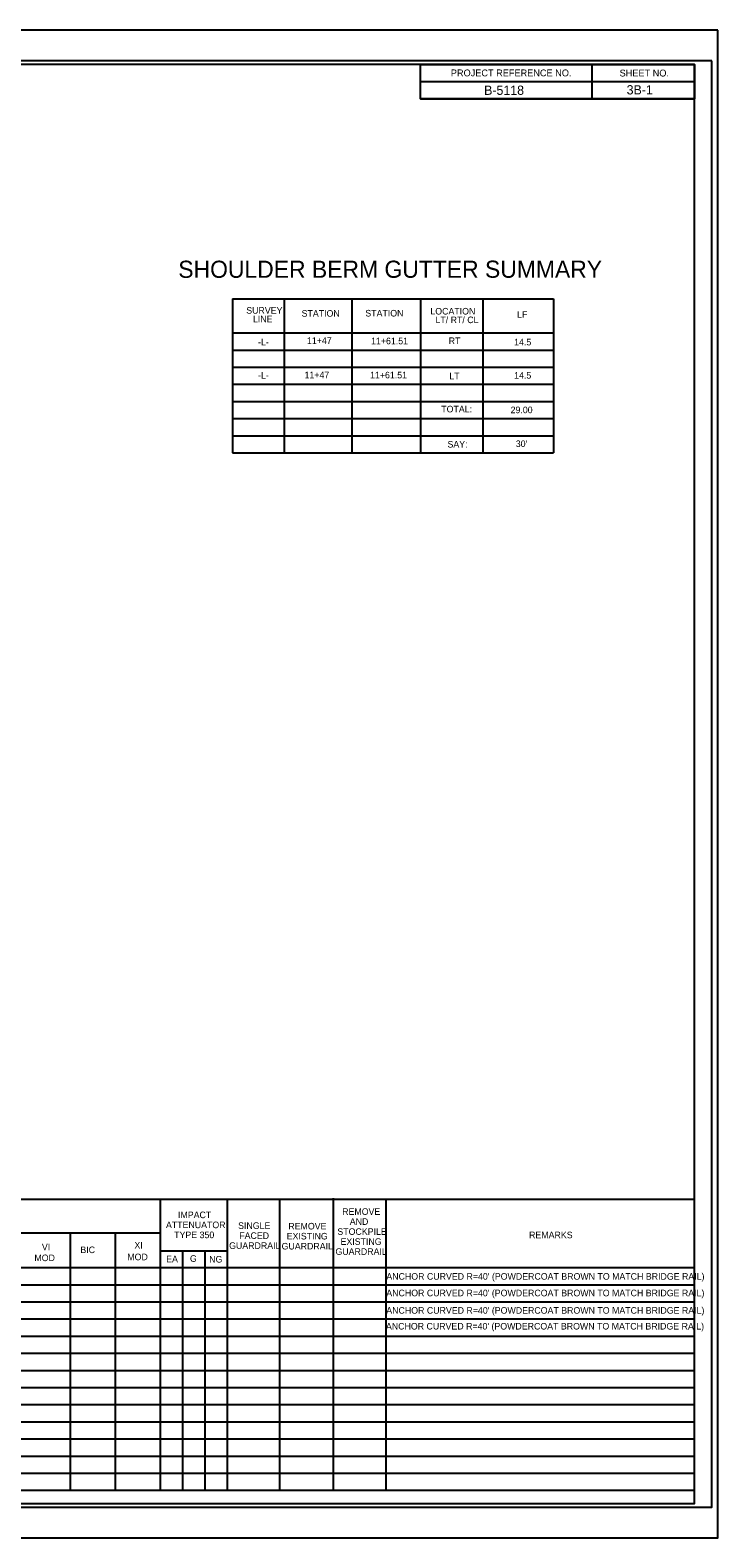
# Model space of a CAD drawing. Extents: x 1729980.3 to 1730027.7, y 539928.4 to 539950.4.
# Drawn here: x 1730003.96 to 1730014, y 539928.38 to 539950.38 of the extents above; entities that cross this region are included whole.
import ezdxf

# ---------------------------------------------------------------- set-up
doc = ezdxf.new("R2010")
doc.units = 0
for name, color, linetype in [('Default', 7, 'Continuous'), ('Sheet Cutting Line CELL', 7, 'Continuous'), ('Sheet Data Field CELL', 7, 'Continuous'), ('Sheet Plot Border Inside CELL', 7, 'Continuous'), ('Sheet Plot Border Outside CELL', 7, 'Continuous'), ('Sheet Summary Combination CELL', 7, 'Continuous'), ('Sheet Summary Combination Grid CELL', 7, 'Continuous')]:
    doc.layers.add(name, color=color, linetype=linetype)

msp = doc.modelspace()

# ---------------------------------------------------------------- linework, layer by layer
at = {"layer": 'Sheet Cutting Line CELL'}
msp.add_line((1730013.998, 539950.377), (1729980.318, 539950.377), dxfattribs=at)
at = {"layer": 'Sheet Plot Border Inside CELL'}
msp.add_lwpolyline([(1730013.908, 539949.928), (1729980.578, 539949.928), (1729980.578, 539928.826), (1730013.908, 539928.826)], close=True, dxfattribs=at)
at = {"layer": 'Sheet Plot Border Outside CELL'}
msp.add_lwpolyline([(1730013.998, 539950.377), (1729980.318, 539950.377), (1729980.318, 539928.377), (1730013.998, 539928.377)], close=True, dxfattribs=at)
at = {"layer": 'Sheet Summary Combination CELL'}
for p, q in [((1730012.158, 539949.876), (1730012.158, 539949.376)), ((1730009.657, 539949.626), (1730013.658, 539949.626)), ((1730009.657, 539949.376), (1730013.658, 539949.376)), ((1730009.737, 539946.458), (1730009.737, 539946.458)), ((1730009.862, 539946.456), (1730009.862, 539946.456)), ((1730010.043, 539946.46), (1730010.043, 539946.46)), ((1730010.155, 539946.458), (1730010.155, 539946.458))]:
    msp.add_line(p, q, dxfattribs=at)
for points in [[(1730013.658, 539949.877), (1729983.658, 539949.877), (1729983.658, 539928.877), (1730013.658, 539928.877)], [(1730009.657, 539949.877), (1730013.658, 539949.877), (1730013.658, 539949.376), (1730009.657, 539949.376)]]:
    msp.add_lwpolyline(points, close=True, dxfattribs=at)
at = {"layer": 'Sheet Summary Combination Grid CELL'}
for p, q in [((1730006.912, 539946.459), (1730011.601, 539946.459)), ((1730006.912, 539946.459), (1730006.912, 539944.209)), ((1730007.668, 539946.459), (1730007.668, 539944.209)), ((1730008.654, 539946.459), (1730008.654, 539944.209)), ((1730009.66, 539946.459), (1730009.66, 539944.209)), ((1730010.568, 539946.45), (1730010.568, 539944.2)), ((1730011.601, 539946.459), (1730011.601, 539944.209)), ((1730006.912, 539945.959), (1730011.601, 539945.959)), ((1730006.912, 539945.709), (1730011.601, 539945.709)), ((1730006.912, 539945.459), (1730011.601, 539945.459)), ((1730006.912, 539945.209), (1730011.601, 539945.209)), ((1730006.912, 539944.959), (1730011.601, 539944.959)), ((1730006.912, 539944.709), (1730011.601, 539944.709)), ((1730006.912, 539944.459), (1730011.601, 539944.459)), ((1730006.912, 539944.209), (1730011.601, 539944.209)), ((1729983.658, 539933.321), (1730013.658, 539933.321)), ((1730005.857, 539933.321), (1730005.857, 539929.071)), ((1730006.834, 539933.321), (1730006.834, 539929.071)), ((1730007.598, 539933.321), (1730007.598, 539929.071)), ((1730008.385, 539933.332), (1730008.385, 539929.082)), ((1730009.151, 539933.321), (1730009.151, 539929.071)), ((1730005.857, 539932.821), (1729996.314, 539932.821)), ((1730004.545, 539932.821), (1730004.545, 539929.071)), ((1730005.201, 539932.821), (1730005.201, 539929.071)), ((1730005.857, 539932.566), (1730006.829, 539932.566)), ((1730006.182, 539932.566), (1730006.184, 539929.071)), ((1730006.509, 539932.566), (1730006.511, 539929.071)), ((1729983.658, 539932.321), (1730013.658, 539932.321)), ((1729983.658, 539932.071), (1730013.658, 539932.071)), ((1729983.658, 539931.821), (1730013.658, 539931.821)), ((1729983.658, 539931.571), (1730013.658, 539931.571)), ((1729983.658, 539931.321), (1730013.658, 539931.321)), ((1729983.658, 539931.321), (1730013.658, 539931.321)), ((1729983.658, 539931.071), (1730013.658, 539931.071)), ((1729983.658, 539930.821), (1730013.658, 539930.821)), ((1729983.658, 539930.571), (1730013.658, 539930.571)), ((1729983.658, 539930.321), (1730013.658, 539930.321)), ((1729983.658, 539930.071), (1730013.658, 539930.071)), ((1729983.658, 539929.821), (1730013.658, 539929.821)), ((1729983.658, 539929.571), (1730013.658, 539929.571)), ((1729983.658, 539929.321), (1730013.658, 539929.321)), ((1729983.658, 539929.071), (1730013.658, 539929.071)), ((1729983.658, 539929.071), (1730013.658, 539929.071))]:
    msp.add_line(p, q, dxfattribs=at)

# ---------------------------------------------------------------- texts
at = {"layer": 'Default'}
for s, p in [('-L-', (1730007.287, 539945.777)), ('11+47', (1730008.001, 539945.799)), ('11+61.51', (1730008.937, 539945.794)), ('RT', (1730010.069, 539945.797)), ('14.5', (1730011.025, 539945.777)), ('-L-', (1730007.287, 539945.292)), ('11+47', (1730007.966, 539945.298)), ('11+61.51', (1730008.922, 539945.296)), ('LT', (1730010.08, 539945.283)), ('14.5', (1730011.025, 539945.292)), ('29.00', (1730010.973, 539944.788)), ("30'", (1730011.049, 539944.294)), ("ANCHOR CURVED R=40' (POWDERCOAT BROWN TO MATCH BRIDGE RAIL)", (1730009.16, 539932.144)), ("ANCHOR CURVED R=40' (POWDERCOAT BROWN TO MATCH BRIDGE RAIL)", (1730009.159, 539931.902)), ("ANCHOR CURVED R=40' (POWDERCOAT BROWN TO MATCH BRIDGE RAIL)", (1730009.159, 539931.648)), ("ANCHOR CURVED R=40' (POWDERCOAT BROWN TO MATCH BRIDGE RAIL)", (1730009.154, 539931.417))]:
    msp.add_text(s, height=0.096, dxfattribs=at).set_placement(p)
at = {"layer": 'Sheet Data Field CELL'}
for s, p in [('B-5118', (1730010.587, 539949.433)), ('3B-1', (1730012.667, 539949.439))]:
    msp.add_text(s, height=0.135, dxfattribs=at).set_placement(p)
at = {"layer": 'Sheet Summary Combination CELL'}
for s, height, p in [('PROJECT REFERENCE NO.', 0.1, (1730010.101, 539949.703)), ('SHEET NO.', 0.1, (1730012.564, 539949.701)), ('SURVEY', 0.096, (1730007.115, 539946.24)), ('STATION', 0.096, (1730007.923, 539946.196)), ('STATION', 0.096, (1730008.853, 539946.199)), ('LOCATION', 0.096, (1730009.802, 539946.228)), ('LF', 0.096, (1730011.068, 539946.18)), ('LINE', 0.096, (1730007.213, 539946.114)), ('LT/ RT/ CL', 0.096, (1730009.877, 539946.102)), ('TOTAL:', 0.096, (1730009.961, 539944.8)), ('SAY:', 0.096, (1730010.052, 539944.287)), ('IMPACT', 0.096, (1730006.119, 539933.042)), ('REMOVE', 0.096, (1730008.515, 539933.09)), ('AND', 0.096, (1730008.626, 539932.944)), ('ATTENUATOR', 0.096, (1730005.943, 539932.896)), ('TYPE 350', 0.096, (1730006.063, 539932.75)), ('SINGLE', 0.096, (1730006.996, 539932.885)), ('FACED', 0.096, (1730007.013, 539932.739)), ('EXISTING', 0.096, (1730007.705, 539932.731)), ('REMOVE', 0.096, (1730007.729, 539932.877)), ('STOCKPILE', 0.096, (1730008.445, 539932.798)), ('REMARKS', 0.096, (1730011.243, 539932.749)), ('VI', 0.096, (1730004.132, 539932.573)), ('BIC', 0.096, (1730004.694, 539932.532)), ('XI', 0.096, (1730005.483, 539932.599)), ('GUARDRAIL', 0.096, (1730006.865, 539932.593)), ('GUARDRAIL', 0.096, (1730007.631, 539932.585)), ('GUARDRAIL', 0.096, (1730008.417, 539932.506)), ('EXISTING', 0.096, (1730008.491, 539932.652)), ('MOD', 0.096, (1730004.023, 539932.415)), ('MOD', 0.096, (1730005.379, 539932.428)), ('EA', 0.096, (1730005.946, 539932.398)), ('G', 0.096, (1730006.293, 539932.405)), ('NG', 0.096, (1730006.574, 539932.394))]:
    msp.add_text(s, height=height, dxfattribs=at).set_placement(p)
msp.add_text('SHOULDER BERM GUTTER SUMMARY', height=0.25, rotation=0.0119, dxfattribs=at).set_placement((1730006.123, 539946.763))

doc.saveas('drawing.dxf')
